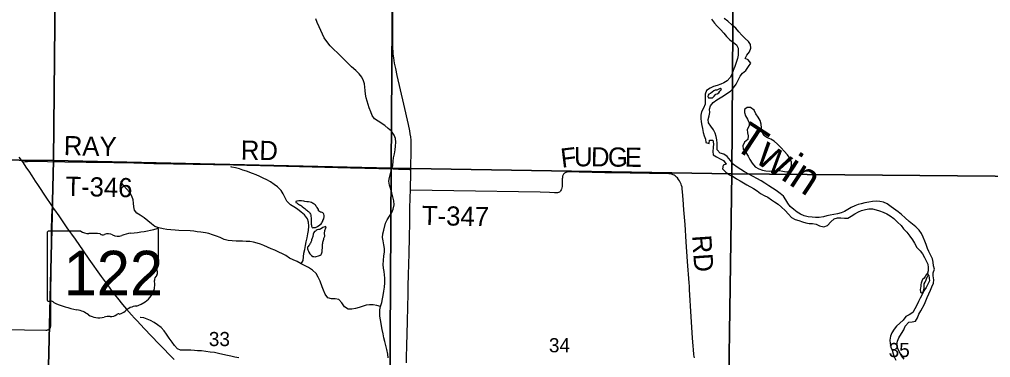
# Model space of a CAD drawing. Extents: x 0 to 34, y 0 to 22.
# Drawn here: x 5.385 to 8.26, y 18.776 to 19.778 of the extents above; entities that cross this region are included whole.
import ezdxf

# ---------------------------------------------------------------- set-up
doc = ezdxf.new("R2010")
doc.units = 0
for name, color, linetype in [('GM_X_Corporation', 7, 'Continuous'), ('GM_X_Major_River', 7, 'Continuous'), ('GM_X_Major_River_Text', 7, 'Continuous'), ('GM_X_Minor_Lake', 7, 'Continuous'), ('GM_X_Minor_River', 7, 'Continuous'), ('GM_X_Section_Text', 7, 'Continuous'), ('GM_X_State_Location', 7, 'Continuous'), ('GM_X_State_Route', 7, 'Continuous'), ('GM_X_State_Shield', 7, 'Continuous'), ('GM_X_Township_Road', 7, 'Continuous'), ('GM_X_Township_Road_Text', 7, 'Continuous')]:
    doc.layers.add(name, color=color, linetype=linetype)

msp = doc.modelspace()

# ---------------------------------------------------------------- linework, layer by layer
at = {"layer": 'GM_X_Corporation'}
for points in [[(4.4842, 20.3804), (5.4958, 20.3705), (5.4859, 19.36), (4.4706, 19.3704)], [(5.4958, 20.3705), (6.4927, 20.3511), (6.4855, 19.3379), (5.4859, 19.36)], [(6.4927, 20.3511), (7.5004, 20.336), (7.4935, 19.3206), (6.4855, 19.3379)], [(7.5004, 20.336), (8.5046, 20.316), (8.496, 19.3116), (7.4935, 19.3206)], [(5.4859, 19.36), (5.4612, 18.3442), (4.4872, 18.3578), (4.4615, 18.3587), (4.4706, 19.3704)], [(6.4855, 19.3379), (6.4791, 18.3297), (5.4991, 18.3437), (5.4612, 18.3442), (5.4859, 19.36)], [(7.4935, 19.3206), (7.4788, 18.3152), (6.4791, 18.3297), (6.4855, 19.3379)], [(8.496, 19.3116), (8.4911, 18.3026), (7.4788, 18.3152), (7.4935, 19.3206)]]:
    msp.add_lwpolyline(points, close=True, dxfattribs=at)
at = {"layer": 'GM_X_Major_River'}
msp.add_line((8.0766, 19.0198), (8.0727, 19.0267), dxfattribs=at)
for points in [[(7.8375, 19.2154), (7.8276, 19.2092), (7.8176, 19.2056), (7.8062, 19.2027), (7.7955, 19.2007), (7.7852, 19.1982), (7.775, 19.1961), (7.765, 19.1936), (7.7525, 19.1916), (7.7415, 19.1914), (7.7313, 19.1924), (7.7195, 19.1933), (7.7082, 19.1962), (7.6973, 19.2013), (7.6875, 19.2068), (7.677, 19.215), (7.6666, 19.2239), (7.6592, 19.2339), (7.654, 19.2439), (7.6463, 19.2546), (7.6366, 19.2624), (7.6249, 19.271), (7.6141, 19.2784), (7.6036, 19.285), (7.5916, 19.2928), (7.5803, 19.2999), (7.5683, 19.3065), (7.557, 19.3128), (7.5439, 19.3195), (7.5311, 19.3266), (7.5202, 19.3332), (7.5097, 19.3403), (7.4989, 19.3488), (7.4896, 19.36), (7.4804, 19.3719), (7.4702, 19.3793), (7.4597, 19.3822), (7.45, 19.3914), (7.4505, 19.4013), (7.4507, 19.4115), (7.4498, 19.421), (7.4473, 19.4317), (7.4441, 19.4413), (7.4397, 19.4512), (7.4315, 19.4616), (7.4249, 19.472), (7.4236, 19.4815), (7.4264, 19.4924), (7.4285, 19.5023), (7.4275, 19.5118), (7.4308, 19.522), (7.4389, 19.5317), (7.4493, 19.5394), (7.4589, 19.5461), (7.4689, 19.552), (7.4792, 19.5586), (7.4896, 19.566), (7.4989, 19.5757), (7.5071, 19.5858), (7.513, 19.5978), (7.5181, 19.6095), (7.5255, 19.6192), (7.5355, 19.627), (7.5429, 19.6387), (7.5496, 19.6484), (7.5425, 19.658), (7.5328, 19.6628), (7.5386, 19.6725), (7.546, 19.6823), (7.5504, 19.6928), (7.5491, 19.7035), (7.5436, 19.713), (7.5335, 19.722), (7.5234, 19.7313), (7.5149, 19.7409), (7.5052, 19.7517), (7.4951, 19.7614), (7.4817, 19.7727), (7.4712, 19.7812)], [(7.434, 19.7785), (7.4425, 19.7673), (7.4503, 19.7577), (7.46, 19.7484), (7.4704, 19.7372), (7.4778, 19.7272), (7.4875, 19.7179), (7.4983, 19.7101), (7.5081, 19.7027), (7.5124, 19.6927), (7.513, 19.6829), (7.5121, 19.6723), (7.5104, 19.662), (7.5064, 19.6507), (7.5023, 19.6387), (7.4976, 19.627), (7.4947, 19.6172), (7.4888, 19.6059), (7.4799, 19.5962), (7.4703, 19.5899), (7.4608, 19.5859), (7.4505, 19.5827), (7.4398, 19.5795), (7.4294, 19.5744), (7.4191, 19.5673), (7.4151, 19.5568), (7.4145, 19.5473), (7.4151, 19.5378), (7.4145, 19.5272), (7.4098, 19.5155), (7.4043, 19.5046), (7.4018, 19.4948), (7.4016, 19.4845), (7.403, 19.475), (7.405, 19.464), (7.4067, 19.4545), (7.4092, 19.4434), (7.4117, 19.4328), (7.416, 19.4232), (7.417, 19.4137), (7.4268, 19.4101), (7.4277, 19.4203), (7.4372, 19.4209), (7.4393, 19.4095), (7.4387, 19.3985), (7.4374, 19.3871), (7.4383, 19.3772), (7.4488, 19.371), (7.4594, 19.3655), (7.4691, 19.36), (7.4773, 19.3496), (7.4677, 19.3467), (7.466, 19.3358), (7.4765, 19.3261), (7.4873, 19.3175), (7.4979, 19.3128), (7.508, 19.3054), (7.5181, 19.2995), (7.5279, 19.294), (7.538, 19.2878), (7.5583, 19.2775), (7.5684, 19.2705), (7.5789, 19.2627), (7.5894, 19.2568), (7.5999, 19.2513), (7.6108, 19.2439), (7.6205, 19.2377), (7.6307, 19.2306), (7.6407, 19.2221), (7.6519, 19.212), (7.6612, 19.2016), (7.6705, 19.1916), (7.6811, 19.1857)], [(7.4594, 19.573), (7.4537, 19.5705), (7.4498, 19.569), (7.4449, 19.5684), (7.4407, 19.5662), (7.4353, 19.5629), (7.4307, 19.5591), (7.4261, 19.5562), (7.4234, 19.5536), (7.4225, 19.5498), (7.4247, 19.546), (7.4297, 19.5455), (7.4361, 19.5458), (7.4419, 19.551), (7.4462, 19.5562)], [(7.4462, 19.5562), (7.4504, 19.558), (7.455, 19.5606), (7.4585, 19.5651), (7.4631, 19.5703), (7.4594, 19.573)], [(8.0043, 18.7716), (7.9957, 18.7816), (7.9906, 18.7923), (7.9851, 18.8034), (7.9823, 18.8137), (7.984, 18.8251), (7.9884, 18.8352), (7.9962, 18.848), (8.0025, 18.8589), (8.0065, 18.869), (8.0173, 18.881), (8.0276, 18.8823), (8.0375, 18.884), (8.043, 18.8945), (8.0477, 18.9047), (8.0532, 18.9144), (8.0638, 18.9347), (8.0725, 18.9543), (8.0773, 18.9652), (8.082, 18.9765), (8.0856, 18.9863), (8.0911, 18.9964), (8.0921, 19.007), (8.09, 19.0181), (8.0902, 19.0279), (8.0938, 19.0381), (8.0913, 19.048), (8.0896, 19.0587), (8.0875, 19.0689), (8.0832, 19.0789), (8.0773, 19.0904), (8.0733, 19.0999), (8.069, 19.111), (8.065, 19.1209), (8.0603, 19.1335), (8.0551, 19.1435), (8.0481, 19.1535), (8.0384, 19.1639), (8.0283, 19.1717), (8.0186, 19.1791), (8.007, 19.1899), (7.9962, 19.2003), (7.9861, 19.2085), (7.9652, 19.2225), (7.9539, 19.2315), (7.9427, 19.237), (7.9321, 19.2387), (7.9211, 19.2393), (7.9104, 19.2384), (7.8998, 19.2363), (7.888, 19.2346), (7.8769, 19.2321), (7.8674, 19.2297), (7.8578, 19.2261), (7.8471, 19.2213), (7.8375, 19.2154)], [(7.6811, 19.1857), (7.6924, 19.1821), (7.7029, 19.1785), (7.7131, 19.1756), (7.7229, 19.1735), (7.7328, 19.1734), (7.743, 19.172), (7.7532, 19.1669), (7.7664, 19.164), (7.7767, 19.168), (7.7868, 19.1784), (7.7968, 19.1877), (7.8067, 19.1906), (7.8166, 19.1904), (7.8276, 19.1891), (7.837, 19.1889), (7.8474, 19.1955), (7.8582, 19.2021), (7.8685, 19.208), (7.8781, 19.2116), (7.8891, 19.2149), (7.899, 19.2169), (7.91, 19.2167), (7.921, 19.2143), (7.9308, 19.2114), (7.9421, 19.207), (7.9523, 19.2027), (7.9624, 19.1964), (7.9733, 19.1883), (7.9844, 19.1778), (7.9949, 19.1678), (8.0023, 19.1581), (8.0116, 19.1477), (8.0205, 19.1358), (8.0282, 19.125), (8.0341, 19.1151), (8.0419, 19.1028), (8.0512, 19.0931), (8.0578, 19.0835), (8.0641, 19.0732), (8.0688, 19.0632), (8.074, 19.0533), (8.0753, 19.0437), (8.0747, 19.0331), (8.0727, 19.0267)], [(8.0766, 19.0198), (8.0788, 19.0042), (8.0744, 18.9941), (8.0689, 18.9843), (8.0626, 18.9742), (8.0568, 18.9637), (8.0512, 18.9528), (8.0461, 18.9426), (8.0414, 18.9317), (8.0359, 18.9208), (8.0292, 18.9103), (8.0185, 18.9033), (8.0085, 18.8982), (8.0007, 18.8877), (7.9911, 18.8788), (7.981, 18.8699), (7.974, 18.8602), (7.9674, 18.8497), (7.9634, 18.8395), (7.9617, 18.8278), (7.963, 18.8179), (7.9647, 18.8076), (7.9683, 18.7981), (7.9719, 18.7878), (7.9748, 18.7782), (7.9796, 18.7683)], [(8.0727, 19.0267), (8.0681, 19.0207), (8.0665, 19.0162), (8.063, 19.0117), (8.0579, 19.0073), (8.056, 19.0024), (8.0539, 18.9964), (8.0535, 18.9933), (8.0531, 18.9899), (8.053, 18.9869), (8.0526, 18.9827), (8.0517, 18.9767), (8.0524, 18.9721), (8.0527, 18.9706), (8.0557, 18.9686), (8.0588, 18.9701), (8.0615, 18.9746), (8.0628, 18.9806), (8.0629, 18.989), (8.0634, 18.995)], [(8.0634, 18.995), (8.0658, 18.9995), (8.0689, 19.0067), (8.0721, 19.0142), (8.0741, 19.0187), (8.0766, 19.0198)]]:
    msp.add_lwpolyline(points, dxfattribs=at)
at = {"layer": 'GM_X_Minor_Lake'}
for points in [[(6.2702, 19.1662), (6.2781, 19.173), (6.2801, 19.1752), (6.2813, 19.1775), (6.2826, 19.1801), (6.2834, 19.1824), (6.2858, 19.1876), (6.2859, 19.1899), (6.2867, 19.1921), (6.2872, 19.1944), (6.2868, 19.1971), (6.2862, 19.2013), (6.2851, 19.2036), (6.2828, 19.2052), (6.2806, 19.2063), (6.2783, 19.2072), (6.276, 19.2076), (6.2729, 19.2088), (6.2707, 19.2108), (6.27, 19.2153), (6.2686, 19.2177), (6.2667, 19.2211), (6.2637, 19.2242), (6.2619, 19.2266), (6.2604, 19.2289), (6.257, 19.2309), (6.2547, 19.2324), (6.2521, 19.234), (6.2491, 19.2356), (6.2452, 19.2365), (6.2411, 19.2377), (6.238, 19.2382), (6.2353, 19.2382), (6.2299, 19.2391), (6.2269, 19.2396), (6.22, 19.2405), (6.2119, 19.2407), (6.2065, 19.2401), (6.203, 19.2383), (6.2034, 19.236), (6.206, 19.2344), (6.2086, 19.232), (6.2113, 19.2305), (6.2143, 19.2293), (6.2166, 19.2277), (6.2196, 19.2257), (6.2219, 19.2241), (6.2271, 19.2202), (6.2298, 19.2179), (6.2332, 19.2155), (6.2354, 19.2135), (6.238, 19.2112), (6.2411, 19.2088), (6.2433, 19.2065), (6.2448, 19.2042), (6.247, 19.2015), (6.2477, 19.1988), (6.248, 19.1965), (6.249, 19.1885), (6.2487, 19.1779), (6.2482, 19.1753), (6.2485, 19.1718), (6.2492, 19.1688), (6.2495, 19.1657), (6.2513, 19.1615)], [(6.2757, 19.1572), (6.2753, 19.1569), (6.2729, 19.1562), (6.2706, 19.1559), (6.266, 19.1545), (6.2633, 19.1531), (6.2609, 19.1512), (6.2586, 19.1494), (6.2569, 19.1468), (6.2553, 19.1445), (6.2545, 19.1423), (6.2532, 19.1355), (6.2523, 19.1325), (6.2515, 19.1302), (6.2498, 19.1249), (6.2494, 19.1227), (6.2477, 19.1181), (6.2461, 19.1155), (6.2445, 19.1129), (6.2433, 19.1107), (6.2413, 19.108), (6.2393, 19.1058), (6.2377, 19.1032), (6.2373, 19.1009), (6.2376, 19.0983), (6.2383, 19.096), (6.2405, 19.0914), (6.2412, 19.0891), (6.2449, 19.0833), (6.2471, 19.0809), (6.2494, 19.0786), (6.2539, 19.0762), (6.2562, 19.0754), (6.2612, 19.0753), (6.2635, 19.0756), (6.2705, 19.0777), (6.2728, 19.0788), (6.2755, 19.0802), (6.2779, 19.0817), (6.2791, 19.084), (6.2799, 19.087), (6.2808, 19.0892), (6.2808, 19.0919), (6.2813, 19.0949), (6.2814, 19.0972), (6.2818, 19.0995), (6.282, 19.1067), (6.2825, 19.1101), (6.2825, 19.1123), (6.283, 19.1158), (6.2831, 19.1184), (6.2839, 19.121), (6.2848, 19.1241), (6.2856, 19.1275), (6.2865, 19.1297), (6.2881, 19.1342), (6.2886, 19.1365), (6.2886, 19.1388), (6.2879, 19.1414), (6.2876, 19.1437), (6.2877, 19.146), (6.2885, 19.1505), (6.2894, 19.1532), (6.2898, 19.1554), (6.2907, 19.1577), (6.2915, 19.1603), (6.2927, 19.1637)], [(6.2513, 19.1615), (6.2536, 19.1611), (6.2559, 19.1614), (6.2582, 19.1613), (6.2609, 19.162), (6.2633, 19.1631), (6.2656, 19.1634), (6.2687, 19.1653), (6.2702, 19.1662)], [(6.2927, 19.1637), (6.2905, 19.1645), (6.2858, 19.1631), (6.2835, 19.1621), (6.2757, 19.1572)]]:
    msp.add_lwpolyline(points, dxfattribs=at)
at = {"layer": 'GM_X_Minor_River'}
for points in [[(6.4834, 19.2778), (6.4809, 19.2873), (6.4785, 19.2988), (6.4806, 19.3101), (6.4831, 19.3218), (6.4859, 19.3331), (6.4907, 19.3456), (6.4909, 19.3581), (6.4923, 19.3679), (6.4955, 19.3804), (6.4972, 19.3914), (6.4982, 19.4027), (6.4992, 19.4145), (6.4979, 19.4251), (6.4943, 19.4351), (6.4865, 19.4466), (6.4768, 19.4547), (6.4667, 19.4637), (6.4472, 19.4769), (6.4363, 19.4836), (6.4293, 19.4932), (6.425, 19.5039), (6.4206, 19.5165), (6.4142, 19.5364), (6.4113, 19.5459), (6.4096, 19.5562), (6.4087, 19.5672), (6.4077, 19.5775), (6.406, 19.587), (6.4031, 19.5965), (6.3984, 19.6069), (6.3902, 19.6169), (6.3809, 19.6265), (6.3682, 19.6374), (6.3582, 19.6471), (6.347, 19.6587), (6.3377, 19.6687), (6.3269, 19.6788), (6.3161, 19.6885), (6.3045, 19.6997), (6.2949, 19.7124), (6.2875, 19.7239), (6.2824, 19.7343), (6.2769, 19.745), (6.2722, 19.7565), (6.2667, 19.7687), (6.262, 19.7798)], [(7.5315, 19.5117), (7.5309, 19.5023), (7.5346, 19.4923), (7.5401, 19.4827), (7.5448, 19.472), (7.5454, 19.4625), (7.5391, 19.4524), (7.5401, 19.4425), (7.5426, 19.433), (7.5412, 19.4228), (7.5316, 19.4142), (7.5261, 19.4037), (7.5274, 19.3942), (7.5356, 19.3834), (7.5426, 19.3727), (7.5473, 19.3631), (7.554, 19.352), (7.5633, 19.3419), (7.5742, 19.3356), (7.5843, 19.332), (7.5949, 19.3296), (7.6055, 19.3286), (7.6154, 19.3299), (7.6249, 19.3305), (7.6344, 19.3307), (7.6446, 19.3286), (7.6544, 19.3269), (7.6647, 19.3286), (7.6707, 19.3452), (7.6709, 19.3555), (7.6654, 19.367), (7.6584, 19.3766), (7.6491, 19.3874), (7.6402, 19.3978), (7.6294, 19.4082), (7.6189, 19.4171), (7.6092, 19.4238), (7.599, 19.4278), (7.5885, 19.4344), (7.5834, 19.4455), (7.5821, 19.4569), (7.5804, 19.4679), (7.5776, 19.4786), (7.5721, 19.489), (7.5646, 19.4982)], [(7.5646, 19.4982), (7.5595, 19.5089), (7.5487, 19.5167), (7.5392, 19.5169), (7.5315, 19.5117)], [(6.2194, 19.0543), (6.2249, 19.0641), (6.2258, 19.0751), (6.2268, 19.0857), (6.2296, 19.0963), (6.2314, 19.108), (6.2335, 19.1193), (6.2363, 19.1314), (6.2385, 19.1428), (6.2402, 19.1533), (6.2412, 19.1655), (6.2406, 19.1776), (6.2374, 19.1872), (6.2289, 19.1995), (6.2191, 19.2069), (6.2083, 19.2162), (6.1971, 19.2232), (6.1869, 19.2291), (6.1769, 19.2399), (6.171, 19.2514), (6.1659, 19.2613), (6.1596, 19.2717), (6.1492, 19.2825), (6.1391, 19.2892), (6.1278, 19.297), (6.1177, 19.3025), (6.1068, 19.308), (6.0966, 19.3127), (6.0857, 19.3175), (6.0748, 19.3219), (6.0571, 19.3286), (6.0465, 19.3319), (6.036, 19.3355), (6.0243, 19.3384), (6.0137, 19.3405), (6.0103, 19.3413)], [(6.4538, 18.9282), (6.4425, 18.9307), (6.4323, 18.9324), (6.4216, 18.9326), (6.4118, 18.9313), (6.4022, 18.9288), (6.3908, 18.9252), (6.3793, 18.922), (6.3687, 18.9203), (6.358, 18.9197), (6.3475, 18.9268), (6.3398, 18.9387), (6.3301, 18.9483), (6.3191, 18.9501), (6.3089, 18.9502), (6.2983, 18.9531), (6.2898, 18.9646), (6.2855, 18.9757), (6.2811, 18.9864), (6.275, 19.0032), (6.2695, 19.0147), (6.2629, 19.0258), (6.2528, 19.0351), (6.2408, 19.0429), (6.231, 19.0484), (6.2194, 19.0543), (6.207, 19.0606), (6.1953, 19.0658), (6.1848, 19.0713), (6.1735, 19.0783), (6.1638, 19.0835), (6.1525, 19.089), (6.1412, 19.0941), (6.1303, 19.0989), (6.1197, 19.1036), (6.1088, 19.108), (6.0986, 19.112), (6.0885, 19.1156), (6.0783, 19.1181), (6.0673, 19.1198), (6.0559, 19.1207), (6.0457, 19.1209), (6.0267, 19.1217), (6.015, 19.1219), (6.0032, 19.1229), (5.9908, 19.1265), (5.9791, 19.1317), (5.9686, 19.136), (5.9561, 19.1404), (5.9459, 19.1437), (5.9357, 19.1458), (5.9221, 19.1475), (5.9111, 19.1493), (5.9013, 19.1506), (5.8907, 19.1519), (5.8566, 19.1525), (5.8463, 19.1535), (5.8334, 19.1545), (5.8213, 19.1562), (5.8104, 19.1576), (5.7979, 19.1605), (5.7862, 19.1649), (5.7757, 19.1726), (5.7649, 19.1816), (5.7537, 19.1905), (5.7424, 19.1979), (5.7323, 19.2038), (5.7253, 19.2134), (5.7232, 19.2233), (5.7226, 19.2336), (5.7213, 19.2435), (5.7177, 19.2549), (5.7118, 19.2657), (5.7014, 19.2761), (5.6925, 19.2865), (5.6862, 19.2965), (5.6847, 19.2977)], [(6.476, 18.7753), (6.4751, 18.7867), (6.4727, 18.8), (6.4699, 18.8122), (6.4663, 18.8244), (6.4639, 18.8347), (6.4614, 18.8469), (6.459, 18.8594), (6.4538, 18.888), (6.4521, 18.899), (6.4519, 18.9085), (6.4521, 18.918), (6.4538, 18.9282), (6.4574, 18.9399), (6.4599, 18.9508), (6.4616, 18.9607), (6.4637, 18.9728), (6.4655, 18.9849), (6.4668, 18.9974), (6.4667, 19.0118), (6.4658, 19.0213), (6.4644, 19.0316), (6.4631, 19.0414), (6.4618, 19.0521), (6.4624, 19.0642), (6.4641, 19.0775), (6.4655, 19.0884), (6.4653, 19.0991), (6.4636, 19.1105), (6.4616, 19.1223), (6.4599, 19.1325), (6.4608, 19.1432), (6.4637, 19.1537), (6.4686, 19.1741), (6.4733, 19.1846), (6.48, 19.1951), (6.487, 19.206), (6.491, 19.2162), (6.4939, 19.229), (6.4933, 19.2404), (6.4901, 19.253), (6.4873, 19.2644), (6.4834, 19.2778)], [(6.0344, 18.7756), (6.0223, 18.7781), (6.0106, 18.7802), (5.9962, 18.7839), (5.9743, 18.7888), (5.9622, 18.791), (5.9497, 18.7927), (5.9372, 18.7948), (5.9236, 18.7962), (5.9122, 18.7968), (5.9028, 18.7974), (5.8921, 18.798), (5.8827, 18.7985), (5.8732, 18.7983), (5.8622, 18.7981), (5.8524, 18.8025), (5.8435, 18.8125), (5.8372, 18.8225), (5.8279, 18.8341), (5.8202, 18.846), (5.8135, 18.8556), (5.8046, 18.8656), (5.7941, 18.8738), (5.7833, 18.8808), (5.7731, 18.8863), (5.7633, 18.8906), (5.7531, 18.8939), (5.7433, 18.8952), (5.7425, 18.8952)]]:
    msp.add_lwpolyline(points, dxfattribs=at)
at = {"layer": 'GM_X_State_Route'}
for points in [[(6.5308, 18.7608), (6.5311, 18.7781), (6.532, 18.811), (6.5339, 18.8831), (6.5347, 18.9266), (6.5355, 18.9638), (6.5361, 18.9887), (6.5369, 19.0216), (6.5383, 19.0849), (6.5394, 19.1334), (6.5404, 19.1769), (6.5411, 19.2172), (6.5419, 19.2502), (6.5422, 19.2723), (6.5435, 19.3262), (6.5436, 19.3336), (6.5447, 19.3952), (6.5446, 19.4114), (6.5442, 19.4207), (6.5433, 19.4301), (6.542, 19.4393), (6.5403, 19.4485), (6.5363, 19.4668), (6.5229, 19.5266), (6.5034, 19.6118), (6.4989, 19.6322), (6.4956, 19.648), (6.4932, 19.664), (6.4917, 19.6756), (6.4909, 19.6844), (6.4904, 19.691), (6.49, 19.6979), (6.49, 19.7059), (6.4907, 19.7736), (6.4915, 19.8842)], [(5.3833, 19.3704), (5.3936, 19.3561), (5.4061, 19.3379), (5.4127, 19.3281), (5.4213, 19.3152), (5.4317, 19.299), (5.4382, 19.2891), (5.4652, 19.2489), (5.4759, 19.2329), (5.4851, 19.2193), (5.4888, 19.2139), (5.5013, 19.196), (5.5257, 19.1608), (5.5496, 19.1267), (5.5734, 19.0925), (5.5907, 19.0683), (5.6271, 19.0164), (5.6501, 18.9847), (5.6609, 18.9702), (5.6751, 18.9521), (5.6905, 18.9334), (5.7017, 18.92), (5.7165, 18.9032), (5.726, 18.8928), (5.7333, 18.8849), (5.7546, 18.8623), (5.7978, 18.8176), (5.8426, 18.771)]]:
    msp.add_lwpolyline(points, dxfattribs=at)
at = {"layer": 'GM_X_State_Shield'}
for p, q in [((5.4669, 19.1469), (5.4669, 18.9468)), ((5.5667, 19.1504), (5.4702, 19.1504)), ((5.7965, 19.0507), (5.7965, 19.1553)), ((5.7965, 19.0507), (5.7965, 19.0507))]:
    msp.add_line(p, q, dxfattribs=at)
for centre, major_axis, start_param, end_param in [((5.4707, 19.1474), (0.00382, 0), 1.712693, 3.28349), ((5.5897, 19.1736), (0.037, 0), 4.042523, 4.731795), ((5.6791, 19.4232), (0.3495, 0), 4.814394, 5.042369), ((5.7929, 19.1558), (0.00367, 0), 6.141152, 7.989035), ((5.602, 19.038), (0.133, 0), 1.404758, 1.657858), ((5.6321, 19.1484), (0.0107, 0), 3.836095, 5.185415), ((5.6478, 19.1253), (0.0222, 0), 0.950623, 2.079405), ((5.6765, 19.157), (0.0267, 0), 4.081561, 5.145723), ((5.7237, 19.0893), (0.0703, 0), 1.699011, 2.107814), ((5.7957, 19.043), (0.00568, 0), 1.883978, 3.671073), ((5.7595, 19.0297), (0.0341, 0), 5.934695, 6.695948), ((5.7926, 19.0503), (0.00393, 0), 5.05454, 6.418171), ((5.6987, 18.9935), (0.0874, 0), 5.101752, 6.440018), ((5.8097, 19.0069), (0.0248, 0), 2.387724, 3.262537), ((5.4707, 18.9464), (0.00385, 0), 3.00124, 4.508301), ((5.4713, 18.9669), (0.0294, 0), 4.665946, 4.897461), ((5.4773, 18.9353), (0.0106, 0), 0.519207, 1.627899), ((5.6112, 19.1151), (0.2524, 0), 4.195997, 4.488961), ((5.5359, 18.8569), (0.079, 0), 0.823519, 1.323587), ((5.7355, 18.8906), (0.0479, 0), 1.647645, 2.488434), ((5.6213, 18.9343), (0.0501, 0), 4.026481, 4.996735), ((5.6503, 18.8651), (0.0412, 0), 1.495662, 1.94098), ((5.6539, 18.9193), (0.0267, 0), 4.691044, 5.507374), ((5.6781, 18.8999), (0.00752, 0), 1.147584, 2.315152), ((5.6749, 18.9274), (0.0282, 0), 4.937069, 5.64225)]:
    msp.add_ellipse(centre, major_axis=major_axis, ratio=0.8, start_param=start_param, end_param=end_param, dxfattribs=at)
at = {"layer": 'GM_X_Township_Road'}
for points in [[(5.3936, 19.3561), (5.4023, 19.357), (5.4091, 19.3576), (5.4165, 19.3578), (5.519, 19.3562), (5.5824, 19.3552), (5.6643, 19.3543), (5.7233, 19.3531), (5.7829, 19.3514), (5.8991, 19.3496), (6.0183, 19.3471), (6.1381, 19.3442), (6.3654, 19.3388), (6.4908, 19.3356), (6.5069, 19.335), (6.5397, 19.3338), (6.5436, 19.3336)], [(7.3831, 18.7753), (7.3822, 18.7794), (7.3816, 18.7851), (7.3804, 18.8006), (7.3797, 18.8105), (7.3778, 18.8353), (7.3735, 18.8975), (7.3689, 18.9784), (7.3684, 18.9876), (7.3677, 18.9976), (7.3623, 19.0607), (7.3586, 19.1196), (7.3554, 19.1705), (7.3519, 19.2138), (7.3497, 19.2451), (7.348, 19.2672), (7.3471, 19.2762), (7.3463, 19.2815), (7.3453, 19.2857), (7.344, 19.2897), (7.3428, 19.2924), (7.3412, 19.2958), (7.3389, 19.3), (7.336, 19.3041), (7.3325, 19.3084), (7.33, 19.3109), (7.3284, 19.3126), (7.3258, 19.3149), (7.3232, 19.3166), (7.3204, 19.318), (7.3182, 19.3188), (7.3148, 19.3198), (7.3112, 19.3205), (7.3071, 19.3209), (7.1925, 19.3222), (7.1178, 19.3235), (7.0415, 19.3257), (7.02, 19.3267), (7.0124, 19.3266), (7.0085, 19.3262), (7.0056, 19.3257), (7.0028, 19.3249), (7.0002, 19.3237), (6.9983, 19.3225), (6.9967, 19.3211), (6.9956, 19.3197), (6.9946, 19.3179), (6.9937, 19.3161), (6.9929, 19.3133), (6.9924, 19.3091), (6.992, 19.3057), (6.9915, 19.2897), (6.9911, 19.2828), (6.9906, 19.2788), (6.9897, 19.2755), (6.9888, 19.2732), (6.9871, 19.2704), (6.9855, 19.2685), (6.9834, 19.2668), (6.9804, 19.2655), (6.9782, 19.2649), (6.975, 19.2644), (6.9693, 19.2643), (6.9538, 19.2651), (6.9265, 19.266), (6.6705, 19.2701), (6.5422, 19.2723)], [(5.3505, 18.8598), (5.4001, 18.859), (5.4629, 18.8575), (5.4661, 18.8578), (5.4684, 18.8582), (5.4704, 18.859), (5.472, 18.8599), (5.4734, 18.8611), (5.4745, 18.8622), (5.4754, 18.8634), (5.4765, 18.8653), (5.4772, 18.8674), (5.4777, 18.8707), (5.4779, 18.8744), (5.4779, 18.9109), (5.4779, 18.9525), (5.4789, 19.0488), (5.4795, 19.1035), (5.4801, 19.1538), (5.4805, 19.1955), (5.4806, 19.1985), (5.481, 19.2016), (5.4816, 19.2054), (5.4827, 19.2095), (5.4851, 19.2193)]]:
    msp.add_lwpolyline(points, dxfattribs=at)

# ---------------------------------------------------------------- texts
at = {"layer": 'GM_X_Major_River_Text'}
msp.add_text('Twin', height=0.0947, rotation=326.7385, dxfattribs=at).set_placement((7.4945, 19.3991))
at = {"layer": 'GM_X_Section_Text'}
for s, p in [('33', (5.9457, 18.8104)), ('34', (6.9524, 18.7921)), ('35', (7.9582, 18.7779))]:
    msp.add_text(s, height=0.04186, rotation=0, dxfattribs=at).set_placement(p)
at = {"layer": 'GM_X_State_Location'}
for s in ['s', 'r']:
    msp.add_text(s, height=0.000189, dxfattribs=at).set_placement((5.628, 19.0336))
msp.add_text('122', height=0.000189, rotation=0, dxfattribs=at).set_placement((5.5612, 19.0198))
at = {"layer": 'GM_X_State_Shield'}
msp.add_text('122', height=0.13184, dxfattribs=at).set_placement((5.5159, 18.9609))
at = {"layer": 'GM_X_Township_Road_Text'}
for s, height, rotation, p in [('RAY', 0.05682, 358.6988, (5.5158, 19.3762)), ('RD', 0.05682, 359.0128, (6.0399, 19.3628)), ('F', 0.0568, 6.9447, (6.9906, 19.3384)), ('U', 0.0568, 359.9199, (7.0268, 19.3429)), ('D', 0.0568, 359.3334, (7.0766, 19.3428)), ('G', 0.0568, 359.3309, (7.1266, 19.3423)), ('E', 0.0568, 359.3314, (7.1766, 19.3417)), ('T-346', 0.05682, 358.5967, (5.5204, 19.2559)), ('T-347', 0.05682, 358.8773, (6.5759, 19.1692)), ('RD', 0.05682, 273.9449, (7.376, 19.1377))]:
    msp.add_text(s, height=height, rotation=rotation, dxfattribs=at).set_placement(p)

doc.saveas('drawing.dxf')
